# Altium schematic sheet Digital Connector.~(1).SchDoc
size A
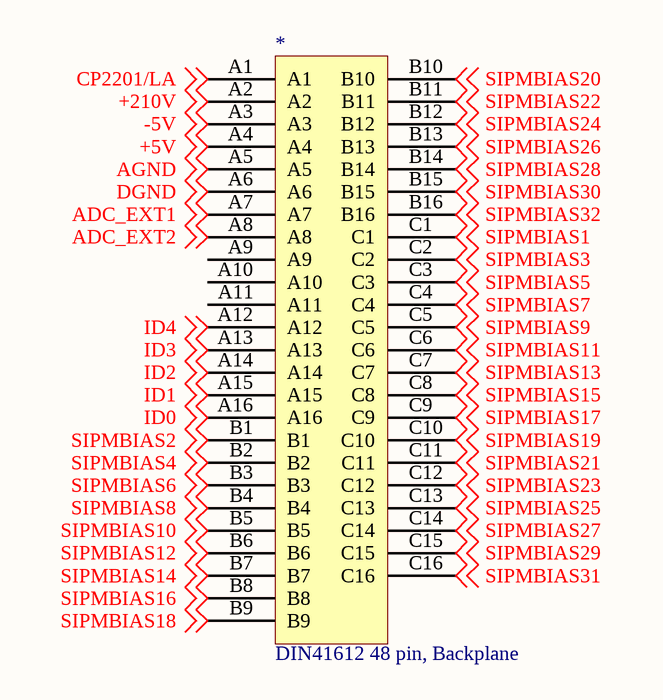
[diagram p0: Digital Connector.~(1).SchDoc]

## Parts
*  DIN41612 48 pin, Backplane  [EURO2.54-2V48]

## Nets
+5V: *.A4 ; off-sheet +5V
+210V: *.A2 ; off-sheet +210V
-5V: *.A3 ; off-sheet -5V
ADC_EXT1: *.A7 ; off-sheet ADC_EXT1
ADC_EXT2: *.A8 ; off-sheet ADC_EXT2
AGND: *.A5 ; off-sheet AGND
CP2201/LA: *.A1 ; off-sheet CP2201/LA
DGND: *.A6 ; off-sheet DGND
ID0: *.A16 ; off-sheet ID0
ID1: *.A15 ; off-sheet ID1
ID2: *.A14 ; off-sheet ID2
ID3: *.A13 ; off-sheet ID3
ID4: *.A12 ; off-sheet ID4
SIPMBIAS1: *.C1 ; off-sheet SIPMBIAS1
SIPMBIAS2: *.B1 ; off-sheet SIPMBIAS2
SIPMBIAS3: *.C2 ; off-sheet SIPMBIAS3
SIPMBIAS4: *.B2 ; off-sheet SIPMBIAS4
SIPMBIAS5: *.C3 ; off-sheet SIPMBIAS5
SIPMBIAS6: *.B3 ; off-sheet SIPMBIAS6
SIPMBIAS7: *.C4 ; off-sheet SIPMBIAS7
SIPMBIAS8: *.B4 ; off-sheet SIPMBIAS8
SIPMBIAS9: *.C5 ; off-sheet SIPMBIAS9
SIPMBIAS10: *.B5 ; off-sheet SIPMBIAS10
SIPMBIAS11: *.C6 ; off-sheet SIPMBIAS11
SIPMBIAS12: *.B6 ; off-sheet SIPMBIAS12
SIPMBIAS13: *.C7 ; off-sheet SIPMBIAS13
SIPMBIAS14: *.B7 ; off-sheet SIPMBIAS14
SIPMBIAS15: *.C8 ; off-sheet SIPMBIAS15
SIPMBIAS16: *.B8 ; off-sheet SIPMBIAS16
SIPMBIAS17: *.C9 ; off-sheet SIPMBIAS17
SIPMBIAS18: *.B9 ; off-sheet SIPMBIAS18
SIPMBIAS19: *.C10 ; off-sheet SIPMBIAS19
SIPMBIAS20: *.B10 ; off-sheet SIPMBIAS20
SIPMBIAS21: *.C11 ; off-sheet SIPMBIAS21
SIPMBIAS22: *.B11 ; off-sheet SIPMBIAS22
SIPMBIAS23: *.C12 ; off-sheet SIPMBIAS23
SIPMBIAS24: *.B12 ; off-sheet SIPMBIAS24
SIPMBIAS25: *.C13 ; off-sheet SIPMBIAS25
SIPMBIAS26: *.B13 ; off-sheet SIPMBIAS26
SIPMBIAS27: *.C14 ; off-sheet SIPMBIAS27
SIPMBIAS28: *.B14 ; off-sheet SIPMBIAS28
SIPMBIAS29: *.C15 ; off-sheet SIPMBIAS29
SIPMBIAS30: *.B15 ; off-sheet SIPMBIAS30
SIPMBIAS31: *.C16 ; off-sheet SIPMBIAS31
SIPMBIAS32: *.B16 ; off-sheet SIPMBIAS32

Not connected (* = marked no-connect by the designer): * A9 A10 A11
